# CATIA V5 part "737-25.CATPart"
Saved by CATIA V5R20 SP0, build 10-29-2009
Part number: 737-25
Definition: NONE
Nomenclature: 737-25
Source: Unknown
Description: 737-25
Bounding box of the stored display mesh (mm): x -31.5 to 23, y -31.46 to 31.46, z -37 to 25
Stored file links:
  C:\Users\Utente\Desktop\IO LAVORO\3D X SITO CF\X SITO\737\737-25.CATPart
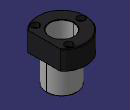
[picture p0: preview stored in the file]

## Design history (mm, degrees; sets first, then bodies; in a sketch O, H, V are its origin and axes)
Body1 "737-25" (main body)
  Solid1: solid without history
